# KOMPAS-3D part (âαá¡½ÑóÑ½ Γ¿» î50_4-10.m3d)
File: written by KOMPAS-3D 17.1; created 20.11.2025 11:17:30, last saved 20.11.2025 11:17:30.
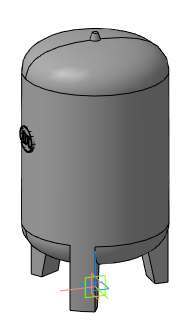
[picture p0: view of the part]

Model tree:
1. Операция без истории:4

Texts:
  REVIT MATERIAL OVERRIDDEN
  REVIT MATERIAL ID
  REVIT SUBCATEGORY ID
  REVIT CATEGORY ID
  REVIT ELEMENT ID
  REVIT BREP TAG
